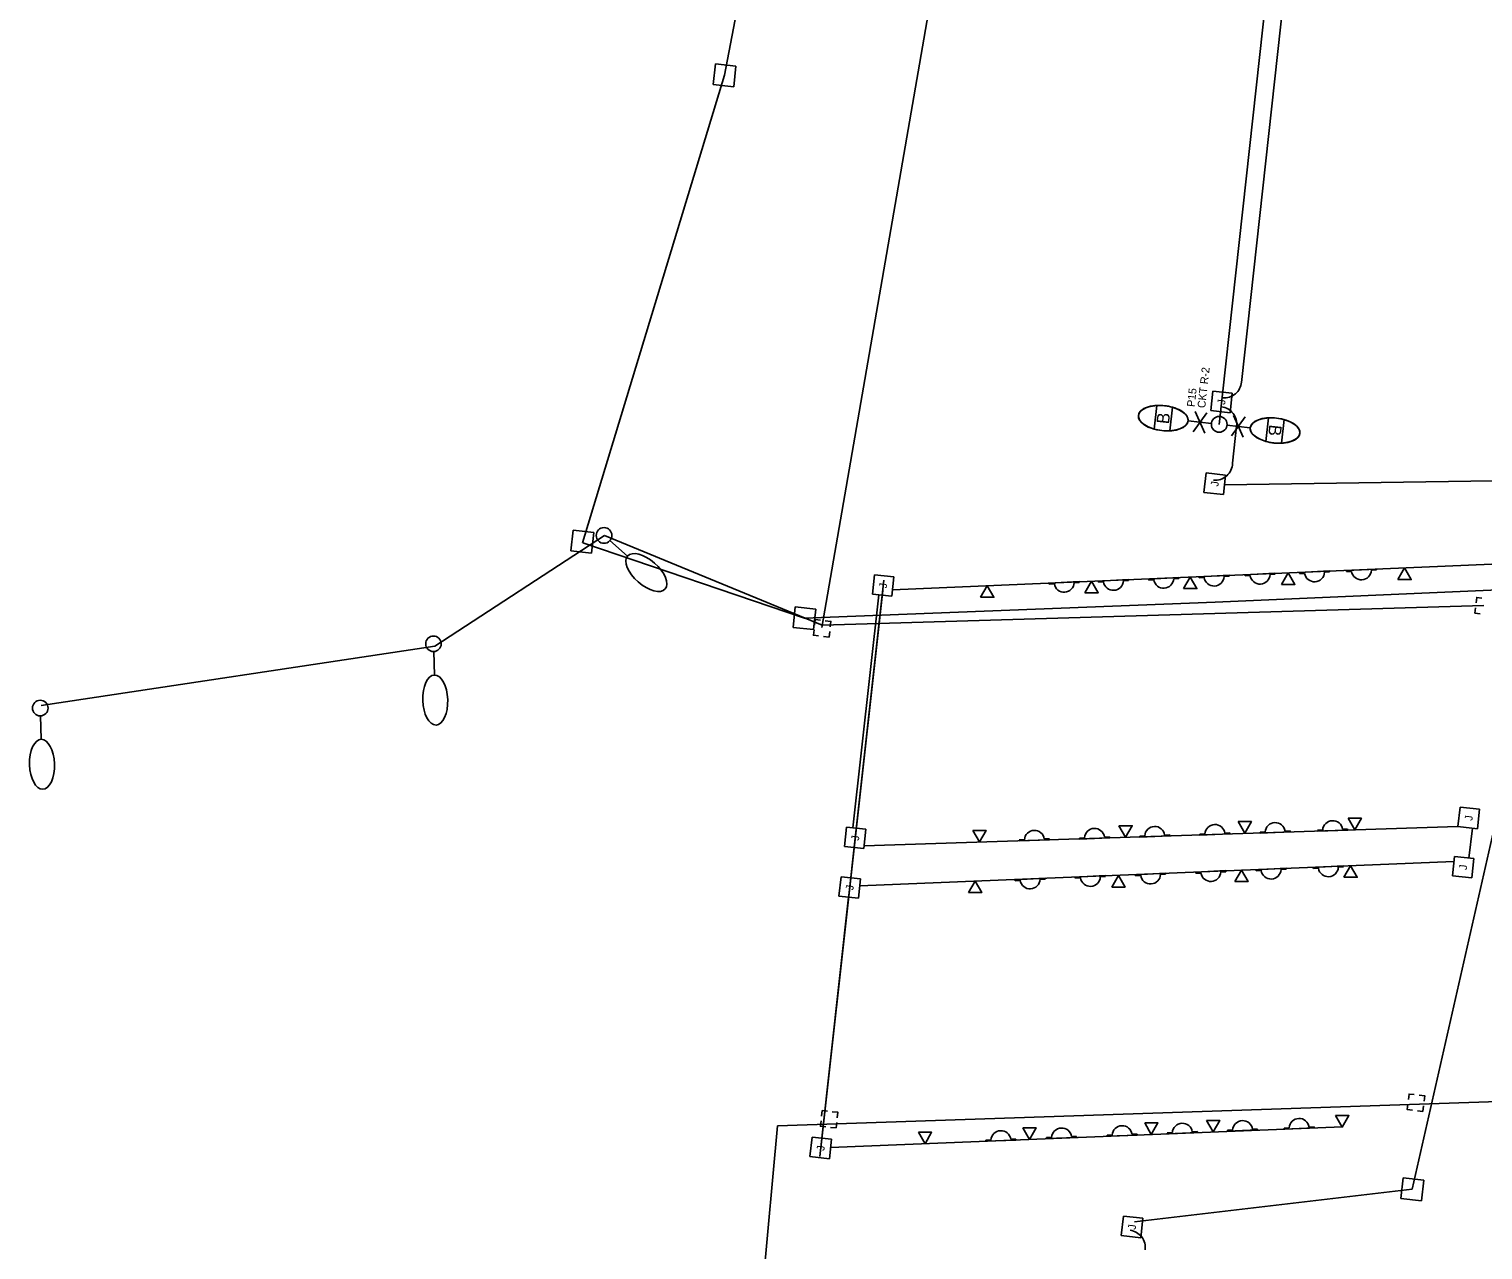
# Model space of a CAD drawing. Extents: x 925407 to 931638, y 609358 to 637063.
# Drawn here: x 930835.1 to 931295.9, y 623954.2 to 624341 of the extents above; entities that cross this region are included whole.
import ezdxf

# ---------------------------------------------------------------- set-up
doc = ezdxf.new("R2010")
doc.units = 0
for name, color, linetype in [('ActivePointCell_dp', 7, 'Continuous'), ('Bridge', 7, 'Continuous'), ('Conduit', 7, 'Continuous'), ('ConduitDB', 7, 'Continuous'), ('ConduitJB', 7, 'Continuous'), ('ConduitOT', 7, 'Continuous'), ('JunctBoxA', 7, 'Continuous'), ('LightingMisc', 7, 'Continuous'), ('LiteCond_ep', 7, 'Continuous'), ('Miscellaneous2', 7, 'Continuous'), ('PoleLight', 7, 'Continuous'), ('PoleLight_ep', 7, 'Continuous'), ('PullBox', 7, 'Continuous'), ('TextLabel', 7, 'Continuous')]:
    doc.layers.add(name, color=color, linetype=linetype)

msp = doc.modelspace()

# ---------------------------------------------------------------- linework, layer by layer
at = {"layer": 'ActivePointCell_dp'}
msp.add_line((931085.71, 623983.77), (931106.08, 624166.4), dxfattribs=at)
at = {"layer": 'Bridge'}
msp.add_line((931086.02, 623986.5), (931105.72, 624163.17), dxfattribs=at)
msp.add_line((931086.02, 623986.5), (931105.72, 624163.17), dxfattribs=at)
msp.add_line((931086.02, 623986.5), (931105.72, 624163.17), dxfattribs=at)
msp.add_line((931086.02, 623986.5), (931105.72, 624163.17), dxfattribs=at)
msp.add_line((931086.02, 623986.5), (931105.72, 624163.17), dxfattribs=at)
at = {"layer": 'Conduit'}
for p, q in [((931122.74, 624360.83), (931086.35, 624151.46)), ((930963.78, 624145.52), (931017.53, 624180.56)), ((931017.53, 624180.56), (931086.47, 624152.15)), ((931086.47, 624152.15), (931296.2, 624158.38)), ((930838.97, 624126.65), (930963.78, 624145.52)), ((931072.34, 623993.5), (931300.82, 624001.21)), ((931062.6, 623887.96), (931072.34, 623993.5))]:
    msp.add_line(p, q, dxfattribs=at)
at = {"layer": 'ConduitDB'}
for p, q in [((931273.51, 623973.41), (931325.4, 624202.39)), ((931213.98, 624196.64), (931310.65, 624198.05)), ((931080.87, 624154.35), (931010.64, 624178.26)), ((931211.01, 624159.49), (931080.87, 624154.35)), ((931305.67, 624163.54), (931211.01, 624159.49)), ((931185.43, 623963.11), (931273.51, 623973.41))]:
    msp.add_line(p, q, dxfattribs=at)
at = {"layer": 'ConduitJB'}
for p, q in [((931108.8, 624163.39), (931298.74, 624171.44)), ((931096.21, 624087.94), (931104.44, 624161.75)), ((931287.98, 624088.32), (931099.82, 624082.22)), ((931291.46, 624078.38), (931292.54, 624087.84)), ((931098.39, 624069.56), (931286.71, 624077.26)), ((931086.36, 623989.58), (931094.88, 624065.96)), ((931089.14, 623986.6), (931251.39, 623993.25))]:
    msp.add_line(p, q, dxfattribs=at)
at = {"layer": 'ConduitOT'}
for p, q in [((931055.56, 624326.38), (931085.24, 624482.71)), ((931219.37, 624229.02), (931233.29, 624355.78)), ((931010.58, 624178.26), (931055.56, 624326.38)), ((931216.53, 624203.46), (931217.82, 624215.18))]:
    msp.add_line(p, q, dxfattribs=at)
for centre, start, end in [((931213.9, 624229.65), 264.8132, 355.292), ((931212.37, 624215.91), 352.3329, 83.1001), ((931211.03, 624203.57), 264.8132, 358.8253), ((931183.4, 623954.95), 352.3329, 83.1001)]:
    msp.add_arc(centre, 5.5, start, end, dxfattribs=at)
at = {"layer": 'LightingMisc'}
for p, q in [((931230, 624168.59), (931220.5, 624168.07)), ((931230.02, 624168.28), (931230, 624168.59)), ((931247.28, 624169.32), (931237.78, 624168.8)), ((931237.78, 624168.8), (931237.79, 624168.48)), ((931237.79, 624168.48), (931239.39, 624168.57)), ((931245.7, 624168.92), (931247.3, 624169.01)), ((931247.3, 624169.01), (931247.28, 624169.32)), ((931262.14, 624169.95), (931252.63, 624169.43)), ((931252.63, 624169.43), (931252.65, 624169.11)), ((931252.65, 624169.11), (931254.25, 624169.2)), ((931260.55, 624169.55), (931262.15, 624169.64)), ((931262.15, 624169.64), (931262.14, 624169.95)), ((931167.95, 624166.02), (931158.45, 624165.49)), ((931158.45, 624165.49), (931158.46, 624165.18)), ((931158.46, 624165.18), (931160.06, 624165.26)), ((931166.37, 624165.61), (931167.97, 624165.7)), ((931167.97, 624165.7), (931167.95, 624166.02)), ((931183.55, 624166.62), (931174.04, 624166.1)), ((931174.04, 624166.1), (931174.06, 624165.78)), ((931174.06, 624165.78), (931175.66, 624165.87)), ((931181.96, 624166.22), (931183.56, 624166.31)), ((931183.56, 624166.31), (931183.55, 624166.62)), ((931199.49, 624167.3), (931189.98, 624166.77)), ((931189.98, 624166.77), (931190, 624166.45)), ((931190, 624166.45), (931191.6, 624166.54)), ((931197.91, 624166.89), (931199.51, 624166.98)), ((931199.51, 624166.98), (931199.49, 624167.3)), ((931215.43, 624167.97), (931205.93, 624167.45)), ((931205.93, 624167.45), (931205.94, 624167.13)), ((931205.94, 624167.13), (931207.54, 624167.22)), ((931213.85, 624167.57), (931215.45, 624167.66)), ((931215.45, 624167.66), (931215.43, 624167.97)), ((931220.5, 624168.07), (931220.52, 624167.75)), ((931220.52, 624167.75), (931222.12, 624167.84)), ((931228.42, 624168.19), (931230.02, 624168.28)), ((931196.63, 624085.72), (931195.03, 624085.65)), ((931196.65, 624085.4), (931196.63, 624085.72)), ((931207.8, 624086.01), (931206.2, 624085.95)), ((931206.2, 624085.95), (931206.21, 624085.63)), ((931206.21, 624085.63), (931215.72, 624086.02)), ((931215.71, 624086.34), (931214.11, 624086.27)), ((931215.72, 624086.02), (931215.71, 624086.34)), ((931226.88, 624086.63), (931225.27, 624086.57)), ((931225.27, 624086.57), (931225.29, 624086.25)), ((931225.29, 624086.25), (931234.8, 624086.64)), ((931234.79, 624086.96), (931233.18, 624086.89)), ((931234.8, 624086.64), (931234.79, 624086.96)), ((931245.11, 624087.22), (931243.51, 624087.16)), ((931243.51, 624087.16), (931243.53, 624086.84)), ((931243.53, 624086.84), (931253.04, 624087.23)), ((931253.02, 624087.55), (931251.42, 624087.48)), ((931253.04, 624087.23), (931253.02, 624087.55)), ((931150.57, 624084.16), (931148.97, 624084.09)), ((931148.97, 624084.09), (931148.98, 624083.77)), ((931148.98, 624083.77), (931158.49, 624084.16)), ((931158.48, 624084.48), (931156.88, 624084.41)), ((931158.49, 624084.16), (931158.48, 624084.48)), ((931169.65, 624084.77), (931168.05, 624084.71)), ((931168.05, 624084.71), (931168.06, 624084.39)), ((931168.06, 624084.39), (931177.57, 624084.78)), ((931177.56, 624085.1), (931175.96, 624085.03)), ((931177.57, 624084.78), (931177.56, 624085.1)), ((931188.72, 624085.39), (931187.12, 624085.33)), ((931187.12, 624085.33), (931187.13, 624085.01)), ((931187.13, 624085.01), (931196.65, 624085.4)), ((931157.13, 624072.03), (931147.62, 624071.5)), ((931155.55, 624071.62), (931157.15, 624071.71)), ((931157.15, 624071.71), (931157.13, 624072.03)), ((931176.22, 624072.81), (931166.72, 624072.28)), ((931166.72, 624072.28), (931166.74, 624071.97)), ((931166.74, 624071.97), (931168.34, 624072.05)), ((931174.64, 624072.4), (931176.24, 624072.49)), ((931176.24, 624072.49), (931176.22, 624072.81)), ((931195.32, 624073.59), (931185.81, 624073.06)), ((931185.81, 624073.06), (931185.83, 624072.75)), ((931185.83, 624072.75), (931187.43, 624072.84)), ((931193.74, 624073.19), (931195.34, 624073.27)), ((931195.34, 624073.27), (931195.32, 624073.59)), ((931214.41, 624074.37), (931204.91, 624073.84)), ((931204.91, 624073.84), (931204.93, 624073.53)), ((931204.93, 624073.53), (931206.53, 624073.62)), ((931212.83, 624073.97), (931214.43, 624074.05)), ((931214.43, 624074.05), (931214.41, 624074.37)), ((931233.51, 624075.15), (931224, 624074.63)), ((931224, 624074.63), (931224.02, 624074.31)), ((931224.02, 624074.31), (931225.62, 624074.4)), ((931231.92, 624074.75), (931233.52, 624074.84)), ((931233.52, 624074.84), (931233.51, 624075.15)), ((931251.65, 624075.89), (931242.14, 624075.37)), ((931242.14, 624075.37), (931242.16, 624075.05)), ((931242.16, 624075.05), (931243.76, 624075.14)), ((931250.06, 624075.49), (931251.66, 624075.58)), ((931251.66, 624075.58), (931251.65, 624075.89)), ((931147.62, 624071.5), (931147.64, 624071.18)), ((931147.64, 624071.18), (931149.24, 624071.27)), ((931139.96, 623989), (931138.36, 623988.93)), ((931138.36, 623988.93), (931138.37, 623988.62)), ((931138.37, 623988.62), (931147.88, 623989.01)), ((931147.87, 623989.32), (931146.27, 623989.26)), ((931147.88, 623989.01), (931147.87, 623989.32)), ((931159.21, 623989.85), (931157.61, 623989.78)), ((931157.61, 623989.78), (931157.62, 623989.47)), ((931157.62, 623989.47), (931167.13, 623989.86)), ((931167.12, 623990.17), (931165.52, 623990.11)), ((931167.13, 623989.86), (931167.12, 623990.17)), ((931178.38, 623990.58), (931176.78, 623990.51)), ((931176.78, 623990.51), (931176.79, 623990.19)), ((931176.79, 623990.19), (931186.3, 623990.58)), ((931186.29, 623990.9), (931184.69, 623990.83)), ((931186.3, 623990.58), (931186.29, 623990.9)), ((931197.47, 623991.36), (931195.87, 623991.29)), ((931195.87, 623991.29), (931195.88, 623990.98)), ((931195.88, 623990.98), (931205.4, 623991.37)), ((931205.38, 623991.68), (931203.78, 623991.62)), ((931205.4, 623991.37), (931205.38, 623991.68)), ((931216.57, 623992.19), (931214.97, 623992.12)), ((931214.97, 623992.12), (931214.98, 623991.81)), ((931214.98, 623991.81), (931224.5, 623992.2)), ((931224.48, 623992.51), (931222.88, 623992.45)), ((931224.5, 623992.2), (931224.48, 623992.51)), ((931234.48, 623992.88), (931232.88, 623992.81)), ((931232.88, 623992.81), (931232.89, 623992.49)), ((931232.89, 623992.49), (931242.4, 623992.88)), ((931242.39, 623993.2), (931240.79, 623993.14)), ((931242.4, 623992.88), (931242.39, 623993.2))]:
    msp.add_line(p, q, dxfattribs=at)
for points in [[(931232.1, 624165.05), (931236.32, 624165.05), (931234.21, 624168.71)], [(931268.97, 624166.62), (931273.18, 624166.62), (931271.08, 624170.27)], [(931136.69, 624161.01), (931140.91, 624161.01), (931138.8, 624164.66)], [(931169.76, 624162.41), (931173.98, 624162.41), (931171.87, 624166.07)], [(931201.03, 624163.74), (931205.25, 624163.74), (931203.14, 624167.39)], [(931253.15, 624090.97), (931257.37, 624090.97), (931255.26, 624087.32)], [(931134.24, 624087.11), (931138.46, 624087.11), (931136.35, 624083.46)], [(931180.52, 624088.61), (931184.74, 624088.61), (931182.63, 624084.96)], [(931218.3, 624089.9), (931222.52, 624089.9), (931220.41, 624086.24)], [(931178.29, 624069.19), (931182.51, 624069.19), (931180.4, 624072.84)], [(931217.23, 624070.92), (931221.45, 624070.92), (931219.34, 624074.57)], [(931251.85, 624072.27), (931256.07, 624072.27), (931253.96, 624075.92)], [(931132.83, 624067.4), (931137.05, 624067.4), (931134.94, 624071.05)], [(931188.7, 623994.45), (931192.91, 623994.45), (931190.8, 623990.8)], [(931208.28, 623995.24), (931212.49, 623995.24), (931210.39, 623991.59)], [(931249.21, 623996.75), (931253.43, 623996.75), (931251.32, 623993.1)], [(931116.97, 623991.48), (931121.19, 623991.48), (931119.08, 623987.82)], [(931150.04, 623992.89), (931154.26, 623992.89), (931152.15, 623989.23)]]:
    msp.add_lwpolyline(points, close=True, dxfattribs=at)
for centre, start, end in [((931242.53, 624169.06), 188.912, 357.4336), ((931257.38, 624169.69), 188.912, 357.4336), ((931163.2, 624165.76), 188.912, 357.4336), ((931178.79, 624166.36), 188.912, 357.4336), ((931194.74, 624167.03), 188.912, 357.4336), ((931210.68, 624167.71), 188.912, 357.4336), ((931225.25, 624168.33), 188.912, 357.4336), ((931248.28, 624087.04), 8.0885, 176.6101), ((931153.74, 624083.97), 8.0885, 176.6101), ((931172.81, 624084.59), 8.0885, 176.6101), ((931191.89, 624085.21), 8.0885, 176.6101), ((931210.97, 624085.82), 8.0885, 176.6101), ((931230.04, 624086.44), 8.0885, 176.6101), ((931171.47, 624072.55), 188.912, 357.4336), ((931190.57, 624073.33), 188.912, 357.4336), ((931209.66, 624074.11), 188.912, 357.4336), ((931228.75, 624074.89), 188.912, 357.4336), ((931246.89, 624075.63), 188.912, 357.4336), ((931152.38, 624071.77), 188.912, 357.4336), ((931181.55, 623990.39), 8.0885, 176.6101), ((931200.64, 623991.17), 8.0885, 176.6101), ((931219.74, 623992), 8.0885, 176.6101), ((931237.65, 623992.69), 8.0885, 176.6101), ((931143.13, 623988.81), 8.0885, 176.6101), ((931162.38, 623989.66), 8.0885, 176.6101)]:
    msp.add_arc(centre, 3.17, start, end, dxfattribs=at)
at = {"layer": 'LiteCond_ep'}
msp.add_line((931212.31, 624215.79), (931241.87, 624484.29), dxfattribs=at)
at = {"layer": 'Miscellaneous2'}
for p, q in [((931192.53, 624221.77), (931191.7, 624214.3)), ((931192.53, 624221.77), (931192.53, 624221.77)), ((931196.67, 624213.75), (931197.5, 624221.21)), ((931197.5, 624221.21), (931197.5, 624221.21)), ((931227.95, 624217.82), (931227.12, 624210.36)), ((931227.95, 624217.82), (931227.95, 624217.82)), ((931232.09, 624209.8), (931232.92, 624217.27)), ((931232.92, 624217.27), (931232.92, 624217.27))]:
    msp.add_line(p, q, dxfattribs=at)
for centre, start_param, end_param in [((931194.6, 624217.76), 1.249648, 1.891946), ((931230.02, 624213.81), 1.249648, 1.891946), ((931194.6, 624217.76), 4.391241, 4.391271), ((931194.6, 624217.76), 4.391271, 5.033538), ((931230.02, 624213.81), 4.391241, 4.391271), ((931230.02, 624213.81), 4.391271, 5.033538)]:
    msp.add_ellipse(centre, major_axis=(7.87, -0.88), ratio=0.5, start_param=start_param, end_param=end_param, dxfattribs=at)
at = {"layer": 'PoleLight'}
for p, q in [((931191.7, 624214.3), (931192.53, 624221.77)), ((931197.5, 624221.21), (931196.67, 624213.75)), ((931209.85, 624216.06), (931202.47, 624216.88)), ((931214.77, 624215.51), (931222.15, 624214.69)), ((931227.12, 624210.36), (931227.95, 624217.82)), ((931232.92, 624217.27), (931232.09, 624209.8))]:
    msp.add_line(p, q, dxfattribs=at)
msp.add_circle((931212.31, 624215.79), 2.48, dxfattribs=at)
msp.add_circle((931212.31, 624215.79), 2.48, dxfattribs=at)
for centre in [(931194.6, 624217.76), (931230.02, 624213.81)]:
    msp.add_ellipse(centre, major_axis=(7.87, -0.88), ratio=0.5, dxfattribs=at)
for centre, start_param, end_param in [((931194.6, 624217.76), 1.891945, 4.391241), ((931194.6, 624217.76), 0.847605, 1.249648), ((931194.6, 624217.76), 0, 0.847605), ((931194.6, 624217.76), 5.033538, 6.283185), ((931230.02, 624213.81), 1.891945, 4.391241), ((931230.02, 624213.81), 0.847605, 1.249648), ((931230.02, 624213.81), 0, 0.847605), ((931230.02, 624213.81), 5.033538, 6.283185)]:
    msp.add_ellipse(centre, major_axis=(7.87, -0.88), ratio=0.5, start_param=start_param, end_param=end_param, dxfattribs=at)
at = {"layer": 'PoleLight_ep'}
for p, q in [((931204.03, 624213.42), (931208.42, 624219.4)), ((931204.73, 624219.81), (931207.72, 624213.01)), ((931209.85, 624216.05), (931202.47, 624216.86)), ((931214.77, 624215.52), (931222.15, 624214.71)), ((931220.58, 624218.15), (931216.19, 624212.17)), ((931219.89, 624211.76), (931216.89, 624218.56)), ((931019.23, 624178.95), (931024.81, 624174.05)), ((930963.38, 624143.78), (930963.62, 624136.36)), ((930838.76, 624123.41), (930838.99, 624115.99))]:
    msp.add_line(p, q, dxfattribs=at)
for centre, radius in [((931212.31, 624215.79), 2.48), ((931017.36, 624180.58), 2.48), ((930963.31, 624146.25), 2.47), ((930838.68, 624125.88), 2.47)]:
    msp.add_circle(centre, radius, dxfattribs=at)
for centre, major_axis in [((931194.59, 624217.72), (-7.87, 0.86)), ((931230.02, 624213.85), (7.87, -0.86)), ((931030.77, 624168.84), (5.96, -5.22)), ((930963.87, 624128.44), (0.25, -7.92)), ((930839.24, 624108.07), (0.25, -7.92))]:
    msp.add_ellipse(centre, major_axis=major_axis, ratio=0.5, dxfattribs=at)
at = {"layer": 'PullBox'}
for p, q in [((931051.95, 624323.49), (931052.67, 624330)), ((931052.67, 624330), (931059.18, 624329.27)), ((931059.18, 624329.27), (931058.46, 624322.77)), ((931058.46, 624322.77), (931051.95, 624323.49)), ((931209.62, 624220.13), (931210.27, 624226.29)), ((931210.27, 624226.29), (931216.43, 624225.64)), ((931216.43, 624225.64), (931215.78, 624219.48)), ((931215.78, 624219.48), (931209.62, 624220.13)), ((931207.49, 624194.21), (931208.15, 624200.37)), ((931208.15, 624200.37), (931214.3, 624199.72)), ((931214.3, 624199.72), (931213.65, 624193.56)), ((931213.65, 624193.56), (931207.49, 624194.21)), ((931006.88, 624175.75), (931007.61, 624182.26)), ((931007.61, 624182.26), (931014.12, 624181.53)), ((931014.12, 624181.53), (931013.39, 624175.02)), ((931013.39, 624175.02), (931006.88, 624175.75)), ((931102.42, 624161.96), (931103.07, 624168.12)), ((931103.07, 624168.12), (931109.23, 624167.47)), ((931109.23, 624167.47), (931108.58, 624161.31)), ((931108.58, 624161.31), (931102.42, 624161.96)), ((931077.26, 624151.46), (931077.98, 624157.97)), ((931077.98, 624157.97), (931084.49, 624157.24)), ((931084.49, 624157.24), (931083.77, 624150.73)), ((931083.77, 624150.73), (931077.26, 624151.46)), ((931287.98, 624088.32), (931288.63, 624094.48)), ((931288.63, 624094.48), (931294.79, 624093.83)), ((931294.79, 624093.83), (931294.14, 624087.67)), ((931093.57, 624081.99), (931094.22, 624088.15)), ((931094.22, 624088.15), (931100.38, 624087.5)), ((931100.38, 624087.5), (931099.73, 624081.34)), ((931294.14, 624087.67), (931287.98, 624088.32)), ((931099.73, 624081.34), (931093.57, 624081.99)), ((931286.23, 624072.71), (931286.88, 624078.87)), ((931286.88, 624078.87), (931293.04, 624078.21)), ((931293.04, 624078.21), (931292.39, 624072.06)), ((931091.82, 624066.28), (931092.47, 624072.44)), ((931092.47, 624072.44), (931098.63, 624071.79)), ((931098.63, 624071.79), (931097.98, 624065.63)), ((931292.39, 624072.06), (931286.23, 624072.71)), ((931097.98, 624065.63), (931091.82, 624066.28)), ((931082.61, 623983.75), (931083.27, 623989.91)), ((931083.27, 623989.91), (931089.42, 623989.25)), ((931089.42, 623989.25), (931088.77, 623983.09)), ((931088.77, 623983.09), (931082.61, 623983.75)), ((931269.9, 623970.52), (931270.62, 623977.03)), ((931270.62, 623977.03), (931277.13, 623976.3)), ((931277.13, 623976.3), (931276.4, 623969.79)), ((931276.4, 623969.79), (931269.9, 623970.52)), ((931181.28, 623958.74), (931181.94, 623964.89)), ((931181.94, 623964.89), (931188.1, 623964.24)), ((931188.1, 623964.24), (931187.44, 623958.08)), ((931187.44, 623958.08), (931181.28, 623958.74))]:
    msp.add_line(p, q, dxfattribs=at)
for points in [[(931295.59, 624160.76), (931293.93, 624160.94), (931293.73, 624159.19)], [(931293.57, 624157.7), (931293.37, 624155.98), (931295.04, 624155.79)], [(931083.91, 624150.67), (931083.72, 624148.95), (931085.38, 624148.76)], [(931085.93, 624153.72), (931084.27, 624153.91), (931084.07, 624152.16)], [(931089.04, 624151.61), (931089.24, 624153.36), (931087.48, 624153.55)], [(931088.69, 624148.39), (931088.88, 624150.11)], [(931086.92, 624148.59), (931088.69, 624148.39)], [(931274.15, 624003.42), (931272.49, 624003.6), (931272.29, 624001.85)], [(931277.26, 624001.3), (931277.46, 624003.05), (931275.69, 624003.24)], [(931088.17, 623998.16), (931086.5, 623998.35), (931086.31, 623996.6)], [(931091.28, 623996.04), (931091.47, 623997.8), (931089.71, 623997.99)], [(931272.13, 624000.36), (931271.93, 623998.64), (931273.6, 623998.45)], [(931275.14, 623998.28), (931276.9, 623998.08)], [(931276.9, 623998.08), (931277.09, 623999.81)], [(931086.14, 623995.11), (931085.95, 623993.38), (931087.62, 623993.2)], [(931090.92, 623992.83), (931091.11, 623994.55)], [(931089.16, 623993.03), (931090.92, 623992.83)]]:
    msp.add_lwpolyline(points, dxfattribs=at)

# ---------------------------------------------------------------- texts
at = {"layer": 'ActivePointCell_dp'}
for s, p in [('CKT R-2', (931207.87, 624220.83)), ('P15', (931204.54, 624221.2))]:
    msp.add_text(s, height=2.5, rotation=83.6425, dxfattribs=at).set_placement(p)
at = {"layer": 'JunctBoxA'}
for p in [(931214.17, 624221.92), (931212.04, 624196), (931106.97, 624163.75), (931292.53, 624090.11), (931098.12, 624083.78), (931290.78, 624074.5), (931096.37, 624068.07), (931087.16, 623985.53), (931185.83, 623960.52)]:
    msp.add_text('J', height=2.48, rotation=83.957, dxfattribs=at).set_placement(p)
at = {"layer": 'TextLabel'}
for rotation, p in [(83.646, (931196.38, 624215.72)), (263.646, (931228.23, 624215.85))]:
    msp.add_text('B', height=4, rotation=rotation, dxfattribs=at).set_placement(p)

doc.saveas('drawing.dxf')
